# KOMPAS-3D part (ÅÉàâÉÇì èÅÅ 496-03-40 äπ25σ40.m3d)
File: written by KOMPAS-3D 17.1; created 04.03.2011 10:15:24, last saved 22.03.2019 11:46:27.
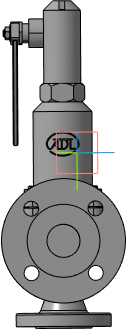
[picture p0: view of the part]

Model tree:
1. Плоскость XY
2. Плоскость ZX
3. Плоскость ZY
4. Ось X
5. Ось Y
6. Ось Z
7. Начало координат
8. Операция без истории:2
